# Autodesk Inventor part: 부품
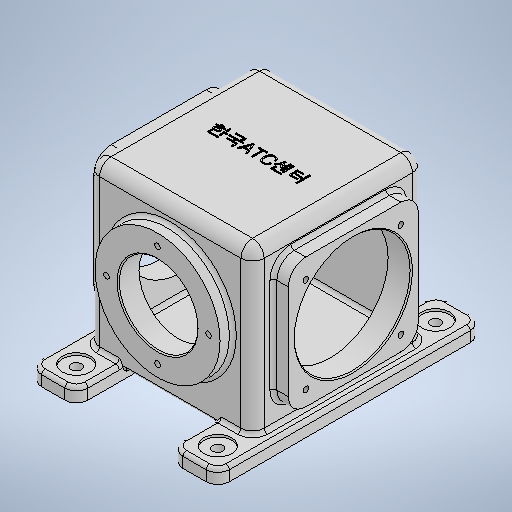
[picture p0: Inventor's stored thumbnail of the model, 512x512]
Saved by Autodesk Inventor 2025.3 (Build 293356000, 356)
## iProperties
Created: 2026-01
Part Number: 부품
Material: 일반
Document SubType Name: Modeling
Designer: pc6
Density: 1 g/cm^3
Appearance: 기본값
Author: pc6
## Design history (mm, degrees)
sketch "스케치1"
  geometry: L1 (71, -72)-(-71, -72); L2 (-71, -72)-(-71, 72); L3 (-71, 72)-(71, 72); L4 (71, 72)-(71, -72); 3 further points
  constraints: 8 end point, 2 midpoint, 2 parallel, 1 horizontal, 1 horizontal alignment, 1 perpendicular, 1 vertical alignment
  dimensions: "d0" = 142 distance between parallel lines of L4 L2; "d1" = 144 distance between parallel lines of L1 L3
extrude "돌출1" new body sketch "스케치1" stored distance "d2" = 148; taper "d3" = 0 deg
sketch "스케치2"
  geometry: L1 (-10, 40)-(30, 40); L2 (30, 40)-(30, -188); L3 (30, -188)-(-10, -188); L4 (-10, -188)-(-10, 40); L5 (112, 40)-(152, 40); L6 (152, 40)-(152, -188); L7 (152, -188)-(112, -188); L8 (112, -188)-(112, 40); 5 further points
  constraints: 16 end point, 4 midpoint, 4 parallel, 2 horizontal, 2 horizontal alignment, 2 perpendicular
  dimensions: "d4" = 40 distance of L2.end L3.end; "d5" = 228 distance between parallel lines of L3 L1; "d6" = 40 distance of L6.end L7.end; "d7" = 228 distance between parallel lines of L7 L5; "d8" = 162 distance from line of point (152, -74) L4; "d9" = 81 distance of point (71, -74) point (-10, -74)
feature "쉘1" dims "d10" = 7
extrude "돌출2" join sketch "스케치2" distance "d11" = 8; taper "d12" = 0 deg; dims "d89" = 4, "d90" = 0
sketch "스케치5"
  geometry: L1 (130, -126)-(18, -126); L2 (18, -126)-(18, -14); L3 (18, -14)-(130, -14); L4 (130, -14)-(130, -126); L5 (130, -126)-(18, -14); L6 (18, -126)-(130, -14); L7 (188, -152)-(-40, -152) reference; 2 further points
  constraints: 12 end point, 2 midpoint, 2 parallel, 1 horizontal, 1 perpendicular, 1 vertical alignment
  dimensions: "d19" = 112 distance of L2.end L3.end; "d20" = 112 distance of L1.end L2.end; "d21" = 82 distance from line of L7 point (74, -70)
extrude "돌출5" join sketch "스케치5" distance "d22" = 13; taper "d23" = 0 deg
sketch "스케치6"
  geometry: L1 (188, -152)-(-40, -152) reference; C1 r 50 at (74, -70); 1 further point
  constraints: 1 centre point, 1 vertical alignment
  dimensions: "d24" = 100 diameter of C1; "d25" = 82 distance from line of L1 C1.centre
extrude "돌출6" cut sketch "스케치6" stored distance "d26" = 13; taper "d27" = 0 deg
sketch "스케치7"
  geometry: L1 (81, -80)-(41, -80) reference; C1 r 54 at (0, 2); C2 r 34 at (0, 2); 1 further point
  constraints: 2 centre point, 1 coincident, 1 vertical alignment
  dimensions: "d28" = 108 diameter of C1; "d29" = 82 distance from line of L1 C1.centre; "d30" = 68 diameter of C2
extrude "돌출7" join sketch "스케치7" distance "d31" = 11; taper "d32" = 0 deg
sketch "스케치8"
  geometry: L1 (81, -82)-(41, -82) reference; C1 r 34 at (0, 0); 2 further points
  constraints: 1 centre point, 1 midpoint, 1 vertical alignment
  dimensions: "d33" = 68 diameter of C1; "d34" = 82 vertical distance of point (61, -82) C1.centre
extrude "돌출8" cut sketch "스케치8" stored distance "d35" = 11; taper "d36" = 0 deg
sketch "스케치9"
  geometry: 5 further points
  constraints: 1 horizontal alignment
  dimensions: "d44" = 82 distance of point (115, -31) point (33, -31); "d45" = 82 distance of point (33, -113) point (33, -31); "d46" = 82 distance of point (33, -113) point (115, -113); "d47" = 82 distance of point (115, -113) point (115, -31); "d48" = 41 horizontal distance of point (74, -72) point (33, -31); "d49" = 41 horizontal distance of point (115, -113) point (74, -72)
hole "구멍1" sketch "스케치9" at (115, -31), (33, -31), (33, -113), (115, -113) diameter "d37" = 4.917; stored, may be unused: countersink angle "d41" = 90 deg, drill point angle "d43" = 118 deg; dims "d38" = 12, "d39" = 4, "d40" = 2, "d42" = 12
sketch "스케치10" dims "d57" = 88
  geometry: L1 (81, -82)-(41, -82) reference; 4 further points
  constraints: 3 vertical alignment, 1 midpoint, 2 other
  dimensions: "d58" = 82 vertical distance of point (61, -82) point (0, 0)
hole "구멍2" sketch "스케치10" at (0, 44) diameter "d50" = 4.917; stored, may be unused: countersink angle "d54" = 90 deg, drill point angle "d56" = 118 deg; dims "d51" = 12, "d52" = 4, "d53" = 2, "d55" = 12
fillet "모깎기1" dims "d62" = 10
fillet "모깎기2" dims "d63" = 10
fillet "모깎기5" dims "d66" = 15
fillet "모깎기6" dims "d67" = 3
chamfer "모따기1" distance "d68" = 1; stored, may be unused: second distance "d69" = 2, angle "d70" = 45 deg
fillet "모깎기7" dims "d71" = 3
sketch "스케치11"
  geometry: C1 r 12 at (10, -20); C2 r 12 at (132, -20); C3 r 12 at (132, 168); C4 r 12 at (10, 168); C5 r 4.5 at (10, -20); C6 r 4.5 at (132, -20); C7 r 4.5 at (132, 168); C8 r 4.5 at (10, 168); 1 further point
  constraints: 8 centre point, 4 coincident, 2 horizontal alignment, 1 vertical alignment
  dimensions: "d72" = 24 diameter of C1; "d73" = 24 diameter of C2; "d74" = 24 diameter of C3; "d75" = 24 diameter of C4; "d76" = 188 distance of C2.centre C3.centre; "d77" = 188 distance of C1.centre C4.centre; "d78" = 122 distance of C4.centre C3.centre; "d79" = 61 horizontal distance of C2.centre point (71, 74); "d80" = 94 vertical distance of C2.centre point (71, 74); "d83" = 9 diameter of C5; "d84" = 9 diameter of C6; "d85" = 9 diameter of C7; "d86" = 9 diameter of C8
extrude "돌출9" cut sketch "스케치11" distance "d81" = 2; taper "d82" = 0 deg
extrude "돌출10" cut sketch "스케치11" extent not by distance; stored distance "d87" = 0; taper "d88" = 0 deg
fillet "모깎기8" dims "d91" = 3
sketch "스케치12"
  geometry: 2 further points
  constraints: 1 other
feature "엠보싱1" sketch "스케치12" dims "d0" = 142, "d1" = 144, "d92" = 0.5, "d93" = 0
feature "ʾ耀ˀ耀˂耀˄耀ˆ耀ˈ耀ˊ耀ˌ耀" dims "d0" = 142, "d1" = 144, "d2" = 148, "d3" = 0, "d4" = 40, "d5" = 228, "d6" = 40, "d7" = 228, "d8" = 162, "d9" = 81, "d10" = 7, "d11" = 8, "d12" = 0, "d19" = 112, "d20" = 112, "d21" = 82, "d22" = 13, "d23" = 0, "d24" = 100, "d25" = 82, "d26" = 13, "d27" = 0, "d28" = 108, "d29" = 82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
node "솔리드1"
mirror "미러1"
pattern_circular "원형 패턴1" dims angle "d60" = 360 deg
node "작업 평면1"
feature "A9D066F2-1C7D-4E18-AEED-F7BC21143FA4" dims "d37" = 4.917, "d38" = 12, "d39" = 4, "d40" = 2, "d41" = 90 deg, "d42" = 12, "d43" = 118 deg
